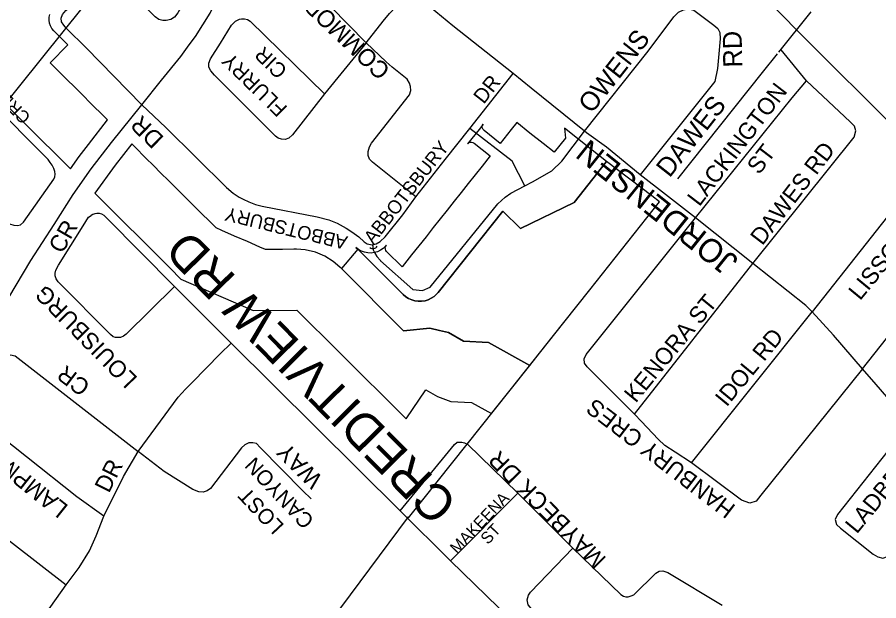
# Model space of a CAD drawing. Extents: x 586326 to 623965, y 4819854 to 4857850.
# Drawn here: x 596086 to 597005, y 4835238 to 4835861 of the extents above; entities that cross this region are included whole.
import ezdxf

# ---------------------------------------------------------------- set-up
doc = ezdxf.new("R2010")
doc.units = 0
for name, color, linetype in [('Lots_Concessions', 7, 'Continuous'), ('Major Rds and Hwys', 7, 'Continuous'), ('Minor Rd Lbls', 7, 'Continuous'), ('Minor Rds', 7, 'Continuous'), ('Park Outlines', 7, 'Continuous'), ('Proposed Major Rds', 7, 'Continuous'), ('Proposed Minor Rds', 7, 'Continuous'), ('Proposed Secondary Rds', 7, 'Continuous'), ('Secondary Rds Lbls', 7, 'Continuous'), ('SWM Ponds', 7, 'Continuous')]:
    doc.layers.add(name, color=color, linetype=linetype)

msp = doc.modelspace()

# ---------------------------------------------------------------- linework, layer by layer
at = {"layer": 'Lots_Concessions'}
for p, q in [((596067.21, 4835760.77), (596157.04, 4835872.33)), ((596898.9, 4835823.64), (596933.22, 4835866.76)), ((596881.56, 4835801.87), (596897.34, 4835821.69)), ((596791.17, 4835688.38), (596881.56, 4835801.87)), ((596669.49, 4835535.14), (596697.09, 4835569.97)), ((596612.27, 4835462.96), (596669.49, 4835535.14)), ((596503.66, 4835326.69), (596612.27, 4835462.96)), ((596330.89, 4835095.27), (596503.89, 4835327.63))]:
    msp.add_line(p, q, dxfattribs=at)
at = {"layer": 'Major Rds and Hwys'}
for points in [[(596219.17, 4835767.54), (596240.45, 4835793.61), (596260.76, 4835818.87), (596269.88, 4835831.43), (596276.47, 4835840.5), (596292.06, 4835865.32), (596300.07, 4835882), (596307.47, 4835901.38), (596314.44, 4835924.24), (596319.68, 4835949.44), (596322.74, 4835973.16), (596323.98, 4836001.46), (596321.22, 4836036.01), (596308.02, 4836117.6)], [(597072.17, 4835701.59), (597014.32, 4835751.04), (596934.34, 4835830.74), (596917.85, 4835847.58)], [(595981.15, 4835415.73), (596015.44, 4835460.04), (596029.14, 4835481.05), (596101.06, 4835601.15), (596125.85, 4835639.86), (596146.17, 4835671.59), (596165.15, 4835699.09), (596187.05, 4835727.37), (596219.17, 4835767.54)]]:
    msp.add_lwpolyline(points, dxfattribs=at)
at = {"layer": 'Minor Rd Lbls'}
msp.add_arc((596465.87, 4835619.56), 5.61, 233.83873, 326.07457, dxfattribs=at)
at = {"layer": 'Minor Rds'}
for points in [[(596295.74, 4836009.01), (596296.67, 4835993.09), (596294.58, 4835962), (596290.31, 4835941.76), (596283.15, 4835917.37), (596273.23, 4835893.25), (596257.62, 4835865.73), (596254.03, 4835861.13), (596250.11, 4835858.64), (596245.29, 4835857.41), (596241.59, 4835857.25), (596237.37, 4835858.6), (596233.65, 4835861.26), (596183.43, 4835911.05)], [(596219.17, 4835767.54), (596159.97, 4835828.25), (596139.07, 4835848.74), (596135.97, 4835852.42), (596133.74, 4835856.13), (596133.16, 4835859.74), (596134.64, 4835863.83), (596138.33, 4835868.16), (596162.69, 4835889.31), (596174.91, 4835901.48), (596183.43, 4835911.05)], [(596458.74, 4835833.44), (596420.65, 4835872.27), (596393.91, 4835899.59)], [(596458.74, 4835833.44), (596476.66, 4835856.54), (596476.86, 4835856.8), (596483.54, 4835865.03), (596490.81, 4835872.44), (596498.5, 4835878.65), (596510.07, 4835887.62)], [(596615.61, 4835800.96), (596551.17, 4835851.7), (596526.76, 4835871.61), (596510.07, 4835887.62)], [(596691.43, 4835739.28), (596759.59, 4835824.77), (596786.93, 4835861.44), (596791.97, 4835866.31), (596797.28, 4835868.75), (596802.19, 4835869.92), (596808.09, 4835868.51), (596829.48, 4835852.61), (596833.7, 4835848.8), (596836.07, 4835844.66)], [(596414.32, 4835779.08), (596379.96, 4835735.29), (596376.19, 4835732), (596372.37, 4835730.56), (596368.36, 4835730.62), (596364.61, 4835731.96), (596361.84, 4835733.99), (596296.78, 4835799.11), (596293.02, 4835803.69), (596290.93, 4835807.71), (596290.81, 4835812.03), (596292.43, 4835816.45), (596303.19, 4835833.28), (596315.06, 4835852.46), (596319.07, 4835856.66), (596323.5, 4835858.8), (596325.65, 4835859.32)], [(596325.65, 4835859.32), (596328.94, 4835859.26), (596332.03, 4835858.56), (596335.03, 4835856.76), (596414.32, 4835779.08)], [(596836.07, 4835844.66), (596836.42, 4835837.68), (596834.73, 4835821.69), (596833.6, 4835806.17), (596830.71, 4835792.23), (596751.04, 4835692.55)], [(596458.74, 4835833.44), (596414.32, 4835779.08)], [(596511.71, 4835669.41), (596465.56, 4835706.17), (596462.11, 4835709.49), (596460.59, 4835713.39), (596460.81, 4835717.78), (596462.03, 4835722.51), (596464.28, 4835726.36), (596504.96, 4835778.08), (596506.25, 4835782.74), (596506.05, 4835786.83), (596504.87, 4835790.61), (596502.23, 4835794.65), (596486.3, 4835807.59), (596480.12, 4835813.38), (596458.74, 4835833.44)], [(596928.52, 4835793.1), (596901.48, 4835825.96)], [(596569.24, 4835742.34), (596615.61, 4835800.96)], [(596691.43, 4835739.28), (596634.68, 4835785.21), (596615.61, 4835800.96)], [(596810.14, 4835646.8), (596913, 4835774.99), (596928.52, 4835793.1)], [(596871.08, 4835598.18), (596979.3, 4835732.94), (596980.92, 4835739.61), (596979.66, 4835744.64), (596974.9, 4835749.33), (596928.52, 4835793.1)], [(596125.51, 4835688.14), (596126.52, 4835690.47), (596126.81, 4835693.25), (596126.58, 4835696.3), (596125.45, 4835699.51), (596123.76, 4835702.9), (596121.65, 4835706.02), (596119.25, 4835709.08), (596055.82, 4835772.68)], [(596219.17, 4835767.54), (596245, 4835743.12), (596309.74, 4835679.07), (596316.65, 4835673.31), (596323.04, 4835669.04), (596327.34, 4835666.78), (596333.29, 4835663.83), (596340.57, 4835661.13), (596347.62, 4835659.31), (596406.44, 4835647.85), (596418.75, 4835644.79), (596427.58, 4835641.17), (596437.36, 4835635.96), (596443.51, 4835632.01), (596450.64, 4835626.42), (596456.43, 4835621.19), (596459.74, 4835619.21), (596463.19, 4835618.34), (596465.36, 4835618.09)], [(596511.71, 4835669.41), (596542.93, 4835708.99), (596569.24, 4835742.34)], [(596751.04, 4835692.55), (596715.06, 4835722.15), (596693.83, 4835737.41), (596691.43, 4835739.28)], [(596017.72, 4835697.46), (596073.03, 4835643.78), (596078.06, 4835640.41), (596082.9, 4835638.84), (596086.57, 4835638.5), (596090.01, 4835639.5), (596093.21, 4835642.06), (596125.51, 4835688.14)], [(596777.89, 4835671.61), (596751.04, 4835692.55)], [(596988.21, 4835485.7), (597102.48, 4835630.33), (597104.76, 4835635.71), (597104.4, 4835640.62), (597101.49, 4835644.27), (597052.42, 4835680.91), (597047.46, 4835682.83), (597042.56, 4835681.75), (597037.62, 4835677.19), (596934.42, 4835546.43)], [(596465.36, 4835618.09), (596469.18, 4835619.18), (596473.52, 4835621.58), (596478.82, 4835626.46), (596497.89, 4835649.97), (596511.71, 4835669.41)], [(596810.14, 4835646.8), (596777.89, 4835671.61)], [(596254.26, 4835573.64), (596202.51, 4835522.71), (596199.83, 4835520.55), (596196.67, 4835519.16), (596193.79, 4835519.1), (596191.22, 4835519.27), (596188.71, 4835519.85), (596185.98, 4835522.18), (596130.01, 4835578.36), (596127.81, 4835581.87), (596126.84, 4835584.8), (596126.76, 4835587.73), (596127.57, 4835591.05), (596130.25, 4835596.37), (596156.6, 4835638.41), (596162.55, 4835647.36), (596165.21, 4835649.44)], [(596745.02, 4835437.27), (596694.4, 4835487.83), (596691.69, 4835491.83), (596691.24, 4835496.42), (596693.29, 4835501.08), (596810.14, 4835646.8)], [(596871.08, 4835598.18), (596810.14, 4835646.8)], [(596745.02, 4835437.27), (596871.08, 4835598.18)], [(596934.42, 4835546.43), (596927.78, 4835553.12), (596871.08, 4835598.18)], [(596805.58, 4835385.34), (596934.42, 4835546.43)], [(596988.21, 4835485.7), (596957.12, 4835521.44), (596934.42, 4835546.43)], [(596215.3, 4835397.42), (596258.24, 4835455.47), (596266.02, 4835464.02), (596273.05, 4835471.15), (596303, 4835501.53), (596314.75, 4835513.05)], [(596178.62, 4835328.39), (596150.08, 4835349.2), (596042.18, 4835434.39), (596039.97, 4835437.52), (596038.93, 4835440.47), (596038.85, 4835443.86), (596041.4, 4835449.97), (596068, 4835493.35), (596070.85, 4835496.99), (596074.28, 4835499.57), (596079.03, 4835500.72), (596084.26, 4835499.44), (596215.3, 4835397.42)], [(596988.21, 4835485.7), (596879.51, 4835350.8), (596874.59, 4835344.51), (596867.86, 4835342.37), (596859.14, 4835345.68), (596805.58, 4835385.34)], [(597042.61, 4835432.79), (597014.21, 4835455.91), (597002.66, 4835468.88), (596988.21, 4835485.7)], [(596805.58, 4835385.34), (596788.33, 4835396.69), (596777.43, 4835403.93), (596769.99, 4835410.51), (596752.3, 4835429.47), (596745.02, 4835437.27)], [(597042.61, 4835432.79), (596961.57, 4835330.19), (596958.85, 4835324.91), (596960.29, 4835319.55), (596964.51, 4835315.72), (596999.53, 4835287.72), (597004.52, 4835284.97), (597009.79, 4835283.74), (597014.78, 4835285.25), (597020.31, 4835289.74), (597099.95, 4835389.91)], [(596400.02, 4835346.77), (596390.93, 4835355.46), (596345.52, 4835401.75), (596341.53, 4835405.82), (596337.67, 4835406.68), (596333.32, 4835406.75), (596329.08, 4835404.56), (596325.59, 4835401.31), (596292.43, 4835357.95), (596288.99, 4835355.38), (596284.71, 4835354.18), (596279.97, 4835354.54), (596273.8, 4835356.73), (596243.12, 4835376.16), (596215.3, 4835397.42)], [(596566.88, 4835405.27), (596620.26, 4835352.97)], [(596178.62, 4835328.39), (596199.68, 4835370.63), (596215.3, 4835397.42)], [(596090.27, 4835190.77), (595943.43, 4835304.89), (595940.44, 4835308.84), (595939.98, 4835312.64), (595940.25, 4835316.53), (595941.76, 4835320.36), (595976.76, 4835365.68), (595980.34, 4835368.73), (595984.28, 4835370.12), (595988.68, 4835370.32), (595993.45, 4835367.61), (596138.5, 4835255.09)], [(596548.75, 4835280.66), (596620.26, 4835352.97)], [(596620.26, 4835352.97), (596679.03, 4835294.35)], [(596138.5, 4835255.09), (596152.34, 4835273.63), (596163.35, 4835291.62), (596170.53, 4835307.36), (596178.62, 4835328.39)], [(596745.27, 4835086.74), (596753.16, 4835095.53), (596754.97, 4835098.47), (596755.77, 4835101.84), (596755.75, 4835105.68), (596753.82, 4835109.91), (596635.47, 4835229.11), (596631.6, 4835233.99), (596630.24, 4835239.02), (596631.72, 4835243.96), (596633.83, 4835247.34), (596679.03, 4835294.35)], [(596679.03, 4835294.35), (596730.43, 4835244.93), (596733.19, 4835243.04), (596735.64, 4835242.45), (596738.18, 4835242.32), (596741.46, 4835243.46), (596744.15, 4835244.53), (596767.6, 4835267.77), (596771.23, 4835269.71), (596775.03, 4835270.17), (596780.59, 4835268.48), (596838.53, 4835233.53)], [(596090.27, 4835190.77), (596116.25, 4835223.52), (596138.5, 4835255.09)]]:
    msp.add_lwpolyline(points, dxfattribs=at)
at = {"layer": 'Park Outlines'}
msp.add_lwpolyline([(596073.33, 4835768.47), (596094.92, 4835746.97), (596143.14, 4835698.96), (596152.62, 4835712.19), (596162.45, 4835725.17), (596182.77, 4835751.26), (596179.56, 4835754.46), (596164.71, 4835769.23), (596156.21, 4835777.69), (596147.71, 4835786.16), (596139.2, 4835794.62), (596135.91, 4835797.89), (596130.35, 4835803.43), (596121.49, 4835812.24), (596140.53, 4835831.37), (596125.41, 4835846.42), (596123.4, 4835848.84), (596121.86, 4835851.58), (596120.86, 4835854.56), (596120.42, 4835857.67), (596120.56, 4835860.81), (596121.28, 4835863.87)], dxfattribs=at)
for points in [[(596208.47, 4835725.68), (596190.85, 4835703.06), (596169.06, 4835673.14), (596249.37, 4835593.18), (596261.09, 4835581.5), (596338.03, 4835547.93), (596384.72, 4835548.22), (596429.72, 4835503.4), (596501.2, 4835432.18), (596522.33, 4835463.37), (596534.77, 4835456.02), (596548.99, 4835450.72), (596570.93, 4835449.69), (596592.3, 4835437.88), (596612.29, 4835462.96), (596633.25, 4835489.4), (596589.02, 4835513.92), (596562.37, 4835515.19), (596546.57, 4835524.55), (596537.04, 4835526.68), (596526.45, 4835529.04), (596498.61, 4835526.4), (596432.15, 4835592.7), (596430.61, 4835594.24), (596423.52, 4835600.36), (596414.39, 4835606.05), (596404.43, 4835610.16), (596393.57, 4835612.62), (596384.29, 4835613.22), (596381.49, 4835613.21), (596369.25, 4835613.13), (596357.01, 4835613.05), (596351.37, 4835613.01), (596345.29, 4835615.67), (596332.09, 4835621.42), (596318.34, 4835627.42), (596304.64, 4835633.4), (596298.49, 4835636.09), (596292.47, 4835642.08), (596281.91, 4835652.58), (596273.16, 4835661.3), (596264.65, 4835669.76), (596256.15, 4835678.22), (596247.65, 4835686.69), (596239.64, 4835694.66), (596231.63, 4835702.63), (596223.62, 4835710.59), (596211.68, 4835722.49)], [(596531.12, 4835563.03), (596528.11, 4835561.02), (596524.85, 4835559.47), (596521.41, 4835558.4), (596517.84, 4835557.84), (596514.23, 4835557.8), (596510.65, 4835558.28), (596507.18, 4835559.27), (596503.88, 4835560.75), (596500.84, 4835562.69), (596498.11, 4835565.05), (596449.69, 4835613.35), (596432.15, 4835592.7), (596498.61, 4835526.4), (596526.45, 4835529.04), (596537.04, 4835526.68), (596546.57, 4835524.55), (596562.37, 4835515.19), (596589.02, 4835513.92), (596633.25, 4835489.4), (596648.97, 4835509.22), (596669.51, 4835535.12), (596697.13, 4835569.96), (596771.67, 4835663.79), (596771.43, 4835663.97), (596763.44, 4835670.32), (596715.12, 4835706.79), (596680.38, 4835663.17), (596623.23, 4835635.42), (596604.34, 4835654.06), (596535.33, 4835567.2), (596533.35, 4835564.99)]]:
    msp.add_lwpolyline(points, close=True, dxfattribs=at)
at = {"layer": 'Proposed Major Rds'}
msp.add_lwpolyline([(596917.85, 4835847.58), (596889.3, 4835876.73), (596878.26, 4835892.55), (596864.51, 4835920.09)], dxfattribs=at)
at = {"layer": 'Proposed Minor Rds'}
for points in [[(596627.83, 4835681.09), (596614.26, 4835707.46), (596569.24, 4835742.34)], [(596627.83, 4835681.09), (596635.95, 4835685.37), (596656.81, 4835697.12), (596667.38, 4835707.27), (596691.43, 4835739.28)], [(596465.36, 4835618.09), (596466.08, 4835612.84), (596467.63, 4835609.78), (596469.87, 4835605.68), (596473.8, 4835601.25), (596473.99, 4835601.08), (596508.45, 4835570.26), (596518.83, 4835569.39), (596526.95, 4835572.74), (596599.06, 4835661.62), (596607.02, 4835668.86), (596612.81, 4835673.18), (596627.83, 4835681.09)], [(596494.75, 4835334.2), (596552.88, 4835404.82), (596555.78, 4835407.32), (596560.54, 4835407.31), (596563.57, 4835406.79), (596566.88, 4835405.27)]]:
    msp.add_lwpolyline(points, dxfattribs=at)
at = {"layer": 'Proposed Secondary Rds'}
for points in [[(596254.26, 4835573.64), (596181.87, 4835646.48), (596179.15, 4835649.21), (596176.59, 4835650.69), (596174.13, 4835651.31), (596171.18, 4835651.54), (596169.04, 4835651.13), (596167.04, 4835650.44), (596165.21, 4835649.44)], [(596314.75, 4835513.05), (596254.26, 4835573.64)], [(596494.75, 4835334.2), (596314.75, 4835513.05)], [(596548.75, 4835280.66), (596494.75, 4835334.2)], [(596651.01, 4835181.12), (596548.75, 4835280.66)]]:
    msp.add_lwpolyline(points, dxfattribs=at)
at = {"layer": 'SWM Ponds'}
msp.add_lwpolyline([(596601.64, 4835726.22), (596584.42, 4835739.9), (596583.37, 4835741.06), (596582.72, 4835742.48), (596582.55, 4835744.03), (596582.85, 4835745.56), (596583.61, 4835746.92), (596580.51, 4835743.01), (596569.94, 4835729.7), (596566.83, 4835725.79), (596567.98, 4835726.85), (596569.4, 4835727.5), (596570.96, 4835727.68), (596572.49, 4835727.37), (596573.85, 4835726.6), (596591.07, 4835712.92), (596582.48, 4835702.11), (596575.02, 4835692.72), (596567.56, 4835683.33), (596560.1, 4835673.94), (596552.63, 4835664.54), (596545.17, 4835655.15), (596537.71, 4835645.76), (596530.25, 4835636.36), (596522.54, 4835626.66), (596514.82, 4835616.95), (596507.11, 4835607.25), (596496.95, 4835594.45), (596480.47, 4835610.88), (596479.58, 4835612.09), (596479.09, 4835613.52), (596479.05, 4835615.03), (596479.45, 4835616.48), (596480.28, 4835617.74), (596479.24, 4835616.58), (596476.7, 4835614.16), (596473.81, 4835612.17), (596470.64, 4835610.67), (596467.27, 4835609.69), (596463.79, 4835609.26), (596460.29, 4835609.38), (596456.85, 4835610.07), (596453.56, 4835611.29), (596450.51, 4835613.02), (596447.77, 4835615.21), (596449.69, 4835613.35), (596498.11, 4835565.05), (596500.84, 4835562.69), (596503.88, 4835560.75), (596507.18, 4835559.27), (596510.65, 4835558.28), (596514.23, 4835557.8), (596517.84, 4835557.84), (596521.41, 4835558.4), (596524.85, 4835559.46), (596528.11, 4835561.02), (596531.12, 4835563.03), (596533.35, 4835564.99), (596535.33, 4835567.2), (596604.34, 4835654.06), (596623.23, 4835635.42), (596680.38, 4835663.16), (596715.12, 4835706.79), (596699.86, 4835718.92), (596670.11, 4835742.55), (596671.31, 4835732.02), (596659.17, 4835716.77), (596647.48, 4835726.05), (596633.39, 4835737.25), (596619.3, 4835748.44), (596613.34, 4835740.93)], close=True, dxfattribs=at)

# ---------------------------------------------------------------- texts
at = {"layer": 'Minor Rd Lbls'}
for s, height, rotation, p in [('COMMODORE', 18.379, 136.50124, (596485.53, 4835805.85)), ('CREDITVIEW            RD', 13.1851, 134.60901, (596101.51, 4835754.93)), ('OWENS ', 20.252, 51.84725, (596699.22, 4835757.16)), ('RD', 20.252, 90.97831, (596859.85, 4835807.41)), ('CIR', 15.951, 135.64753, (596375.62, 4835805.12)), ('FLURRY', 15.951, 135.64753, (596375.5, 4835764.58)), ('DR', 15.757, 51.84725, (596584.09, 4835767.37)), ('LACKINGTON', 17.937, 52.54824, (596814.07, 4835658.03)), ('DAWES', 20.252, 51.84725, (596782.33, 4835688.8)), ('DR', 18.48, 135.23589, (596243.98, 4835732.36)), ('ABBOTSBURY', 14.469, 51.84725, (596466.24, 4835617.67)), ('JORDENSEN     ', 25.002, 141.32709, (596857.11, 4835603.07)), ('ST', 17.937, 52.54824, (596877.74, 4835691.99)), ('DAWES RD', 17.937, 52.54824, (596881.25, 4835616.4)), ('ABBOTSBURY', 14.572, 166.29072, (596439.69, 4835626.81)), ('CR', 17.937, 60.12838, (596134.38, 4835607.67)), ('LISSON', 17.937, 50.56754, (596985.52, 4835557.77)), ('LOUISBURG', 17.937, 134.60901, (596215.6, 4835475.91)), ('KENORA ST', 17.937, 50.56754, (596746.17, 4835448.46)), ('IDOL RD', 17.937, 50.56754, (596843.22, 4835444.27)), ('CR', 17.937, 142.67944, (596165.47, 4835469.49)), ('HANBURY CRES', 17.9367, 142.54824, (596853.85, 4835339.06)), ('LADBROOK', 17.937, 50.56754, (596982.04, 4835308.75)), ('LAMPMAN', 17.937, 141.51233, (596141.94, 4835339.16)), ('WAY', 18.119, 134.68625, (596413.29, 4835368.84)), ('MAYBECK DR', 18.529, 134.66566, (596715.74, 4835283.37)), ('DR', 17.937, 63.52648, (596184.2, 4835352.22)), ('CANYON', 16.398, 133.21492, (596404.1, 4835324.44)), ('LOST ', 16.398, 133.21492, (596371.98, 4835318.72)), ('MAKEENA', 12.529, 46.51807, (596555.86, 4835287.3)), (' ST', 12.529, 46.51807, (596585.27, 4835294.08))]:
    msp.add_text(s, height=height, rotation=rotation, dxfattribs=at).set_placement(p)
at = {"layer": 'Secondary Rds Lbls'}
msp.add_text('CREDITVIEW RD', height=38.449, rotation=134.60901, dxfattribs=at).set_placement((596557.92, 4835343.37))

doc.saveas('drawing.dxf')
